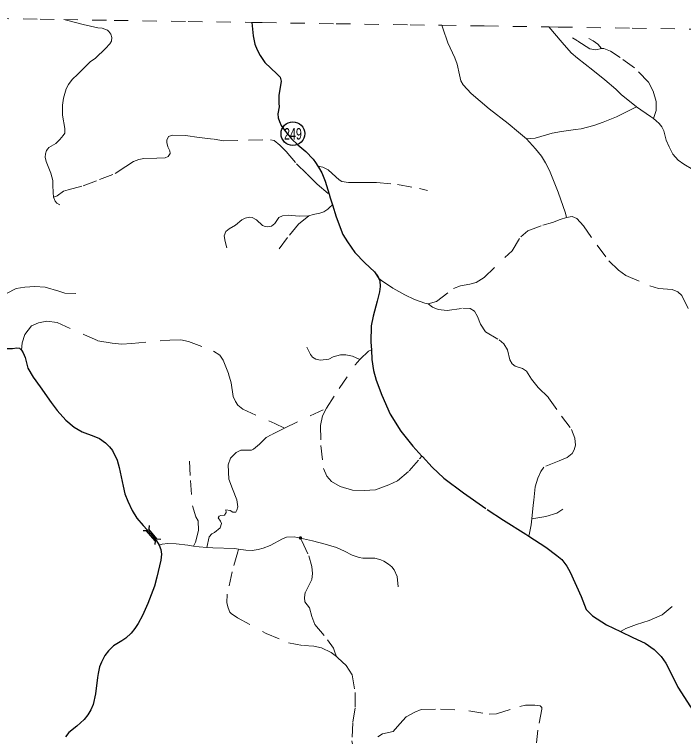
# Model space of a CAD drawing. Extents: x 703.1 to 728.9, y 7316.2 to 7344.3.
# Drawn here: x 714.18 to 718.88, y 7339.1 to 7344.17 of the extents above; entities that cross this region are included whole.
import ezdxf
from ezdxf.enums import TextEntityAlignment as Align

# ---------------------------------------------------------------- set-up
doc = ezdxf.new("R2010")
doc.units = 0
doc.header["$LTSCALE"] = 0.032
doc.header["$PDMODE"] = 32
doc.header["$PDSIZE"] = 0.016
for name, pattern in [('DOTTED', [1.5, 0.3, -1.2]), ('LONG_DASHED', [7.5, 6, -1.5]), ('MEDIUM_DASHED', [4.5, 3, -1.5]), ('SHORT_DASHED', [2.7, 1.5, -1.2])]:
    doc.linetypes.add(name, pattern=pattern)
for name, color, linetype, lineweight in [('10', 7, 'Continuous', 25), ('13', 7, 'Continuous', 25), ('4', 7, 'LONG_DASHED', 25), ('5', 7, 'LONG_DASHED', 13), ('58', 7, 'SHORT_DASHED', 13), ('6', 7, 'MEDIUM_DASHED', 13), ('7', 7, 'DOTTED', 13)]:
    doc.layers.add(name, color=color, linetype=linetype, lineweight=lineweight)
doc.layers.add('61', color=7, linetype='Continuous')

msp = doc.modelspace()

# ---------------------------------------------------------------- linework, layer by layer
at = {"layer": '10'}
for p, q in [((715.1256, 7340.5838), (715.1238, 7340.5589)), ((715.1838, 7340.4886), (715.1238, 7340.5589)), ((715.1686, 7340.4756), (715.1665, 7340.4508)), ((715.2086, 7340.4867), (715.1838, 7340.4886))]:
    msp.add_line(p, q, dxfattribs=at)
msp.add_lwpolyline([(715.1686, 7340.4756), (715.1085, 7340.546), (715.0836, 7340.5479)], dxfattribs=at)
at = {"layer": '13'}
msp.add_circle((716.1347, 7343.3322), 0.083, dxfattribs=at)
at = {"layer": '4'}
for points in [[(715.8465, 7344.1122), (715.8561, 7344.0171), (715.8682, 7343.9608), (715.8843, 7343.9196), (715.9054, 7343.8813), (715.9386, 7343.832), (716.0221, 7343.7515), (716.0447, 7343.7274), (716.0527, 7343.7002), (716.0487, 7343.669), (716.0366, 7343.6016), (716.0366, 7343.5463), (716.0382, 7343.5192), (716.0291, 7343.4709), (716.0311, 7343.4427), (716.0412, 7343.4166), (716.0527, 7343.3894), (716.0758, 7343.3572), (716.1261, 7343.2958), (716.1704, 7343.2546), (716.2257, 7343.2073), (716.2774, 7343.1529), (716.2935, 7343.1308), (716.3107, 7343.1037)], [(716.3107, 7343.1037), (716.3146, 7343.0976), (716.3378, 7343.0573), (716.3619, 7342.999), (716.3886, 7342.9073)], [(716.3886, 7342.9073), (716.3956, 7342.8832), (716.4115, 7342.8328)], [(716.4115, 7342.8328), (716.4379, 7342.7495), (716.4861, 7342.6257), (716.5173, 7342.5734), (716.5696, 7342.4999), (716.6404, 7342.4255), (716.7068, 7342.3631), (716.7367, 7342.3168)], [(716.7367, 7342.3168), (716.7259, 7342.342), (716.744, 7342.2997), (716.747, 7342.2595), (716.742, 7342.2233), (716.7265, 7342.1579), (716.6973, 7342.0532), (716.6828, 7341.9838), (716.6818, 7341.8701), (716.6851, 7341.8165)], [(713.9656, 7341.9306), (713.9923, 7341.8937), (714.0266, 7341.8582), (714.0544, 7341.8381), (714.088, 7341.8297), (714.1196, 7341.8252), (714.1681, 7341.8265), (714.1982, 7341.831), (714.2176, 7341.8271), (714.2318, 7341.8142)], [(714.2318, 7341.8142), (714.2422, 7341.7948), (714.2557, 7341.7625), (714.2755, 7341.6881), (714.313, 7341.6254), (714.3611, 7341.5556), (714.438, 7341.4476), (714.4804, 7341.3907), (714.5418, 7341.3228), (714.6, 7341.2737), (714.6572, 7341.242), (714.7386, 7341.2097), (714.7793, 7341.1935), (714.8207, 7341.1651), (714.8491, 7341.1366), (714.8691, 7341.1108), (714.9011, 7341.0423), (714.916, 7340.9899), (714.9435, 7340.8599), (714.9562, 7340.8075), (714.9768, 7340.7539), (715.0079, 7340.6886), (715.0411, 7340.6356), (715.0838, 7340.5832), (715.1413, 7340.5237), (715.1785, 7340.4778), (715.1973, 7340.4474)], [(716.6851, 7341.8165), (716.6893, 7341.7484), (716.7008, 7341.671), (716.7179, 7341.6046), (716.7581, 7341.4989), (716.817, 7341.3651), (716.8929, 7341.2464), (716.9764, 7341.1418), (717.0399, 7341.0716)], [(717.0399, 7341.0716), (717.0438, 7341.0673), (717.1106, 7340.9939), (717.1941, 7340.9154), (717.3308, 7340.8128), (717.4973, 7340.6971), (717.6119, 7340.6207), (717.7698, 7340.5231), (717.7896, 7340.5103)], [(717.7896, 7340.5103), (717.908, 7340.4335), (717.9854, 7340.3741), (718.0216, 7340.346), (718.0568, 7340.2987), (718.0795, 7340.2574), (718.1579, 7340.0854), (718.1926, 7339.9948), (718.2359, 7339.9505), (718.3344, 7339.8871), (718.4328, 7339.8406)], [(715.1973, 7340.4474), (715.2082, 7340.4157), (715.2128, 7340.3821), (715.2079, 7340.3407), (715.1808, 7340.2224), (715.163, 7340.159)], [(715.163, 7340.159), (715.1164, 7340.0375), (715.0806, 7339.9522), (715.0502, 7339.8959), (715.025, 7339.861), (715.0007, 7339.8287), (714.9619, 7339.7944)], [(718.4328, 7339.8406), (718.5195, 7339.7996), (718.6054, 7339.7584), (718.6698, 7339.7141), (718.7191, 7339.6658), (718.7512, 7339.6186), (718.7774, 7339.5693), (718.8352, 7339.4515), (718.9247, 7339.3127), (719.0326, 7339.1695)], [(714.9619, 7339.7944), (714.9341, 7339.7757), (714.8766, 7339.7395), (714.8411, 7339.7045), (714.8162, 7339.6722), (714.7923, 7339.6263), (714.7787, 7339.5939), (714.7683, 7339.5474), (714.7638, 7339.5177), (714.75, 7339.4039), (714.7341, 7339.3289), (714.718, 7339.292), (714.6973, 7339.2565), (714.6708, 7339.2242), (714.62, 7339.177), (714.5625, 7339.133), (714.5392, 7339.1014)]]:
    msp.add_lwpolyline(points, dxfattribs=at)
at = {"layer": '5'}
for points in [[(714.5271, 7344.132), (714.5471, 7344.127), (714.6633, 7344.0979), (714.7675, 7344.0744), (714.7976, 7344.0715), (714.8342, 7344.0568), (714.8438, 7344.0487), (714.8577, 7344.0304), (714.8643, 7344.0061), (714.8621, 7343.9812), (714.8504, 7343.9621), (714.821, 7343.9298), (714.7499, 7343.8623), (714.7132, 7343.8358), (714.6269, 7343.7484), (714.5866, 7343.7117), (714.5602, 7343.6772), (714.5455, 7343.6464), (714.526, 7343.5803), (714.5179, 7343.5326), (714.5179, 7343.4621), (714.5359, 7343.3689), (714.5345, 7343.3366), (714.5242, 7343.3197), (714.5007, 7343.2903), (714.4714, 7343.2632), (714.4226, 7343.2353), (714.4152, 7343.2258), (714.4071, 7343.2147), (714.3998, 7343.1898), (714.3976, 7343.167), (714.4042, 7343.1369), (714.4365, 7343.0562), (714.4508, 7343.0048), (714.4508, 7342.9762), (714.4522, 7342.916), (714.4544, 7342.8918), (714.456, 7342.8875)], [(717.1801, 7344.092), (717.187, 7344.072), (717.2221, 7343.9697), (717.2707, 7343.8636), (717.2881, 7343.8203), (717.3041, 7343.7443), (717.313, 7343.703), (717.3284, 7343.6743), (717.385, 7343.613), (717.512, 7343.507), (717.6447, 7343.4044), (717.718, 7343.3431), (717.7733, 7343.2957)], [(718.544, 7343.5211), (718.4374, 7343.6071), (718.4011, 7343.6445), (718.3238, 7343.7105), (718.2385, 7343.7778), (718.1309, 7343.8605), (718.0876, 7343.8985), (718.023, 7343.9705), (717.9299, 7344.0806)], [(717.7733, 7343.2957), (717.8353, 7343.3011), (717.9539, 7343.3358), (718.0192, 7343.3478), (718.1162, 7343.3604), (718.1575, 7343.3658), (718.2458, 7343.3891), (718.3111, 7343.4118), (718.4051, 7343.4498), (718.544, 7343.5211)], [(718.544, 7343.5211), (718.6438, 7343.4536), (718.6636, 7343.4378)], [(718.6636, 7343.4378), (718.6834, 7343.4219), (718.7035, 7343.4024), (718.7217, 7343.3805), (718.7357, 7343.3513), (718.7534, 7343.2867), (718.7741, 7343.2399), (718.8, 7343.1893), (718.8371, 7343.1473), (718.8779, 7343.1175), (718.9399, 7343.0809), (718.9883, 7343.0536)], [(717.7733, 7343.2957), (717.8365, 7343.2266), (717.879, 7343.1734), (717.9074, 7343.1278), (717.9346, 7343.0728), (717.9953, 7342.9207), (718.0464, 7342.7745), (718.0533, 7342.7443)], [(714.456, 7342.8875), (714.4666, 7342.858), (714.4783, 7342.8448), (714.4988, 7342.8331)], [(715.7534, 7340.4192), (715.8049, 7340.4113), (715.8482, 7340.4091), (715.8907, 7340.4163), (715.9259, 7340.4247), (715.9761, 7340.4437), (716.063, 7340.4918), (716.0904, 7340.5035), (716.1434, 7340.5057), (716.1658, 7340.5013), (716.1878, 7340.4963)], [(716.1878, 7340.4963), (716.2716, 7340.4773), (716.3618, 7340.4538), (716.4405, 7340.4298), (716.4975, 7340.4035), (716.5508, 7340.3756), (716.5994, 7340.3593), (716.6262, 7340.3549), (716.71, 7340.3549), (716.7521, 7340.3437), (716.7722, 7340.3337), (716.8052, 7340.3135), (716.8286, 7340.2934), (716.8443, 7340.2733), (716.8655, 7340.2258), (716.8736, 7340.1531)], [(715.1973, 7340.4474), (715.2171, 7340.4543), (715.2584, 7340.4582), (715.3171, 7340.4554), (715.3986, 7340.4454), (715.4377, 7340.4395)], [(715.4377, 7340.4395), (715.4768, 7340.4336), (715.532, 7340.4307)], [(715.532, 7340.4307), (715.5729, 7340.4286), (715.7251, 7340.4236), (715.7534, 7340.4192)]]:
    msp.add_lwpolyline(points, dxfattribs=at)
at = {"layer": '58'}
for points in [[(712.0937, 7344.1682), (712.2844, 7344.1654), (712.8036, 7344.1577), (713.3228, 7344.15), (713.842, 7344.1422), (714.3612, 7344.1345), (714.5271, 7344.132)], [(714.5271, 7344.132), (714.8804, 7344.1267), (715.3996, 7344.1189), (715.8465, 7344.1122)], [(715.8465, 7344.1122), (715.9188, 7344.1111), (716.438, 7344.1032), (716.9572, 7344.0954), (717.1801, 7344.092)], [(717.1801, 7344.092), (717.4764, 7344.0875), (717.9299, 7344.0806)], [(717.9299, 7344.0806), (717.9956, 7344.0796), (718.5148, 7344.0717), (719.034, 7344.0638), (719.5532, 7344.0558), (719.8674, 7344.051)]]:
    msp.add_lwpolyline(points, dxfattribs=at)
at = {"layer": '6'}
for points in [[(718.0533, 7342.7443), (718.0932, 7342.7503), (718.1268, 7342.7363), (718.1723, 7342.6857), (718.269, 7342.5491), (718.3509, 7342.4406), (718.4192, 7342.3748), (718.4707, 7342.3365), (718.6395, 7342.2651), (718.6986, 7342.2452), (718.7947, 7342.2395), (718.8346, 7342.2237), (718.8624, 7342.1965), (718.9354, 7342.0487)], [(717.0837, 7342.1381), (717.1429, 7342.1556), (717.2605, 7342.2454), (717.3111, 7342.2644), (717.3762, 7342.2771), (717.4199, 7342.2878), (717.4768, 7342.3245), (717.6721, 7342.5111), (717.7335, 7342.6098), (717.7819, 7342.6512), (717.8887, 7342.6898), (717.9564, 7342.7101), (718.0101, 7342.7297), (718.0533, 7342.7443)], [(716.7367, 7342.3168), (716.7567, 7342.3031), (716.835, 7342.2496), (716.9189, 7342.2029), (716.9888, 7342.1682), (717.0591, 7342.1441), (717.0837, 7342.1381)], [(717.0837, 7342.1381), (717.1136, 7342.1162), (717.1538, 7342.0992), (717.2176, 7342.0921), (717.3269, 7342.1079), (717.3791, 7342.1054), (717.4077, 7342.0868), (717.4296, 7342.0489), (717.4501, 7341.9951), (717.4865, 7341.9426), (717.5805, 7341.8873), (717.6144, 7341.8579), (717.6405, 7341.8162), (717.6571, 7341.7453), (717.6729, 7341.7169), (717.6935, 7341.7013), (717.7463, 7341.6858), (717.7739, 7341.6662), (717.8091, 7341.6099), (717.8551, 7341.5514), (717.9284, 7341.4805), (718.0186, 7341.3516), (718.0902, 7341.2574), (718.1131, 7341.1963), (718.1161, 7341.1486), (718.1085, 7341.1154), (718.0942, 7341.0895), (718.059, 7341.0614), (718.0023, 7341.0368), (717.8958, 7340.9945), (717.8729, 7340.9631), (717.8523, 7340.9169), (717.8333, 7340.8546), (717.8245, 7340.7624), (717.8205, 7340.7272), (717.8109, 7340.6315)], [(714.2318, 7341.8142), (714.2367, 7341.8658), (714.2546, 7341.9236), (714.3015, 7341.9844), (714.3493, 7342.0063), (714.409, 7342.0173), (714.4817, 7342.0083), (714.6719, 7341.9216), (714.7675, 7341.8788), (714.8671, 7341.8618), (714.9329, 7341.8549), (715.0041, 7341.8614), (715.272, 7341.8843), (715.3481, 7341.8858), (715.4029, 7341.8748), (715.5772, 7341.8071), (715.6225, 7341.7777), (715.6464, 7341.7448), (715.6832, 7341.6482), (715.7017, 7341.5849), (715.7166, 7341.4893), (715.7316, 7341.4544), (715.7475, 7341.4275), (715.7833, 7341.3996), (716.0089, 7341.2995), (716.0757, 7341.2676), (716.3699, 7341.4076)], [(716.605, 7341.7489), (716.6084, 7341.7528), (716.6622, 7341.8056), (716.6651, 7341.807), (716.6851, 7341.8165)], [(716.3699, 7341.4076), (716.4586, 7341.5441), (716.5726, 7341.712), (716.605, 7341.7489)], [(716.3699, 7341.4076), (716.3415, 7341.3523), (716.3286, 7341.2846), (716.33, 7341.1446), (716.3505, 7340.9837), (716.3734, 7340.9299), (716.4062, 7340.893), (716.4655, 7340.8576), (716.5522, 7340.8327), (716.6338, 7340.8307), (716.7145, 7340.8347), (716.8066, 7340.8691), (716.8683, 7340.898), (716.951, 7340.9667), (717.023, 7341.0516), (717.0399, 7341.0716)], [(716.0757, 7341.2676), (715.9825, 7341.2193), (715.9477, 7341.2003), (715.9009, 7341.1545), (715.859, 7341.1187), (715.8441, 7341.1127), (715.7943, 7341.1127), (715.77, 7341.1122), (715.7361, 7341.0963), (715.6963, 7341.0554), (715.6813, 7341.0086), (715.6863, 7340.909), (715.7106, 7340.8417), (715.7405, 7340.764), (715.7485, 7340.7142), (715.7425, 7340.6913), (715.7355, 7340.6774), (715.7146, 7340.6784), (715.6957, 7340.6893), (715.6638, 7340.6953), (715.6658, 7340.6754), (715.6559, 7340.6564), (715.629, 7340.6544), (715.617, 7340.6505), (715.6116, 7340.637), (715.6265, 7340.6151), (715.6335, 7340.5972), (715.6235, 7340.5673), (715.5837, 7340.5344), (715.5668, 7340.5265), (715.5478, 7340.5055), (715.532, 7340.4307)], [(717.8109, 7340.6315), (717.8067, 7340.5893), (717.7939, 7340.5303), (717.7896, 7340.5103)], [(715.7534, 7340.4192), (715.7479, 7340.3992), (715.7092, 7340.2588), (715.6745, 7340.1021), (715.6705, 7340.0429), (715.6808, 7340.0069), (715.6932, 7339.9766), (715.7012, 7339.9677), (715.7457, 7339.9374), (715.9468, 7339.8279), (716.103, 7339.7607), (716.208, 7339.742), (716.281, 7339.7376), (716.3353, 7339.726), (716.4042, 7339.6936), (716.44, 7339.6648)], [(716.44, 7339.6648), (716.4496, 7339.6571), (716.5092, 7339.6036), (716.5501, 7339.5369), (716.5711, 7339.4135), (716.5711, 7339.3049), (716.5546, 7339.1995), (716.5492, 7339.0748), (716.5702, 7338.964), (716.5764, 7338.9248)], [(716.7312, 7339.1029), (716.7633, 7339.1225), (716.8371, 7339.1394), (716.8852, 7339.1937), (716.9292, 7339.2432), (716.9897, 7339.2752), (717.0342, 7339.293), (717.1712, 7339.2966), (717.3692, 7339.2845), (717.5107, 7339.2623), (717.5623, 7339.2632), (717.7265, 7339.3143), (717.7675, 7339.3232), (717.8324, 7339.3241), (717.8689, 7339.3188), (717.8805, 7339.3072), (717.8805, 7339.2965), (717.8529, 7339.1479), (717.844, 7339.0597)]]:
    msp.add_lwpolyline(points, dxfattribs=at)
at = {"layer": '7'}
for points in [[(718.3, 7343.9301), (718.2586, 7343.9196), (718.2166, 7343.927), (718.1302, 7343.9826), (718.0956, 7344.0036)], [(718.3, 7343.9301), (718.2728, 7343.9598), (718.2413, 7343.9839), (718.2104, 7343.9999)], [(718.6636, 7343.4378), (718.6828, 7343.4953), (718.6828, 7343.5571), (718.663, 7343.63), (718.6284, 7343.6942), (718.5309, 7343.7943), (718.4296, 7343.8671), (718.3629, 7343.9104), (718.3148, 7343.9289), (718.3, 7343.9301)], [(714.456, 7342.8875), (714.476, 7342.8946), (714.4815, 7342.8966), (714.5254, 7342.9278), (714.5582, 7342.9378), (714.6635, 7342.9654), (714.7777, 7343.0098), (714.888, 7343.0524), (714.9621, 7343.1022), (715.0163, 7343.1379), (715.0538, 7343.1516), (715.0893, 7343.159), (715.1802, 7343.1606), (715.2398, 7343.162), (715.2593, 7343.1715), (715.2747, 7343.1921), (715.2715, 7343.2128), (715.2583, 7343.2408), (715.2498, 7343.2694), (715.2514, 7343.2869), (715.2612, 7343.3125), (715.2913, 7343.321), (715.3807, 7343.3183), (715.4775, 7343.3046), (715.5831, 7343.2932), (715.6487, 7343.2815), (715.8235, 7343.2871), (715.9771, 7343.2895), (716.0025, 7343.2837), (716.0427, 7343.252), (716.0882, 7343.207), (716.1606, 7343.1207), (716.2339, 7343.048), (716.3051, 7342.9773), (716.3886, 7342.9073)], [(716.3107, 7343.1037), (716.3455, 7343.0967), (716.381, 7343.0787), (716.4354, 7343.0305), (716.4587, 7343.0072), (716.4772, 7342.9977), (716.5259, 7342.9893), (716.6192, 7342.9895), (716.7213, 7342.9895), (716.8696, 7342.9755), (717.0238, 7342.9467), (717.0799, 7342.9335)], [(716.4115, 7342.8328), (716.3915, 7342.8144), (716.3792, 7342.8031), (716.3512, 7342.785), (716.3247, 7342.7744), (716.2771, 7342.7646), (716.2468, 7342.757)], [(716.2468, 7342.757), (716.1788, 7342.754), (716.1024, 7342.7615), (716.0608, 7342.7555), (716.0366, 7342.7449), (716.0071, 7342.7033), (715.9837, 7342.6836), (715.9564, 7342.6791), (715.9413, 7342.6806), (715.9209, 7342.6889), (715.8785, 7342.7267), (715.8486, 7342.7445), (715.8305, 7342.746), (715.7995, 7342.7392), (715.776, 7342.7279), (715.7322, 7342.6901), (715.6868, 7342.6651), (715.6645, 7342.6458), (715.6524, 7342.6155), (715.66, 7342.5754), (715.6705, 7342.5315)], [(716.2468, 7342.757), (716.175, 7342.698), (716.0979, 7342.6041), (716.0325, 7342.5175)], [(713.9656, 7341.9306), (713.9891, 7342.0191), (714.0278, 7342.1015), (714.0676, 7342.1558), (714.1267, 7342.212), (714.1945, 7342.2469), (714.2555, 7342.2566), (714.3243, 7342.2614), (714.3979, 7342.2547), (714.4928, 7342.2265), (714.5355, 7342.213), (714.612, 7342.211)], [(716.605, 7341.7489), (716.5538, 7341.7708), (716.5056, 7341.7807), (716.468, 7341.7813), (716.4172, 7341.7666), (716.3863, 7341.7498), (716.3287, 7341.7441), (716.2957, 7341.7519), (716.2727, 7341.765), (716.2585, 7341.7844), (716.2329, 7341.8342)], [(715.4102, 7341.0359), (715.4163, 7340.9008), (715.431, 7340.7227), (715.4531, 7340.644), (715.4703, 7340.617), (715.4728, 7340.5482), (715.4519, 7340.4684), (715.4377, 7340.4395)], [(717.8109, 7340.6315), (717.9087, 7340.6463), (717.9855, 7340.6711), (718.0293, 7340.6991)], [(716.1878, 7340.4963), (716.1972, 7340.4763), (716.2462, 7340.3717), (716.2681, 7340.2963), (716.2725, 7340.2482), (716.2672, 7340.2061), (716.2208, 7340.1141), (716.2169, 7340.0804), (716.2177, 7340.048), (716.2501, 7340.0059), (716.2668, 7339.9455), (716.2895, 7339.8911), (716.3784, 7339.7829), (716.4204, 7339.7233), (716.4318, 7339.69), (716.44, 7339.6648)], [(718.4328, 7339.8406), (718.4528, 7339.8525), (718.4692, 7339.8623), (718.5439, 7339.8911), (718.6342, 7339.9185), (718.7253, 7339.9585), (718.7956, 7340.0163)]]:
    msp.add_lwpolyline(points, dxfattribs=at)
msp.add_point((716.1878, 7340.4963), dxfattribs=at)

# ---------------------------------------------------------------- texts
at = {"layer": '61', "width": 0.7}
msp.add_text('249', height=0.08, dxfattribs=at).set_placement((716.1349, 7343.2911), align=Align.CENTER)

doc.saveas('drawing.dxf')
